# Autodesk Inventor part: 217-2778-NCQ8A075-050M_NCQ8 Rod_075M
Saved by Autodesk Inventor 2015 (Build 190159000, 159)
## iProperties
Created: 2014-11
Part Number: 217-2778-NCQ8A075-050M_NCQ8 Rod_075M
Material: Generic
Document SubType Name: Modeling
Designer: User
Density: 1 g/cm^3
Appearance: Default
Author: User
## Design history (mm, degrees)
node "217-2778-NCQ8A075-050M_NCQ8 Rod_075M.ipt1"
node "External Rod Thread Chamfer"
node "Base1"
